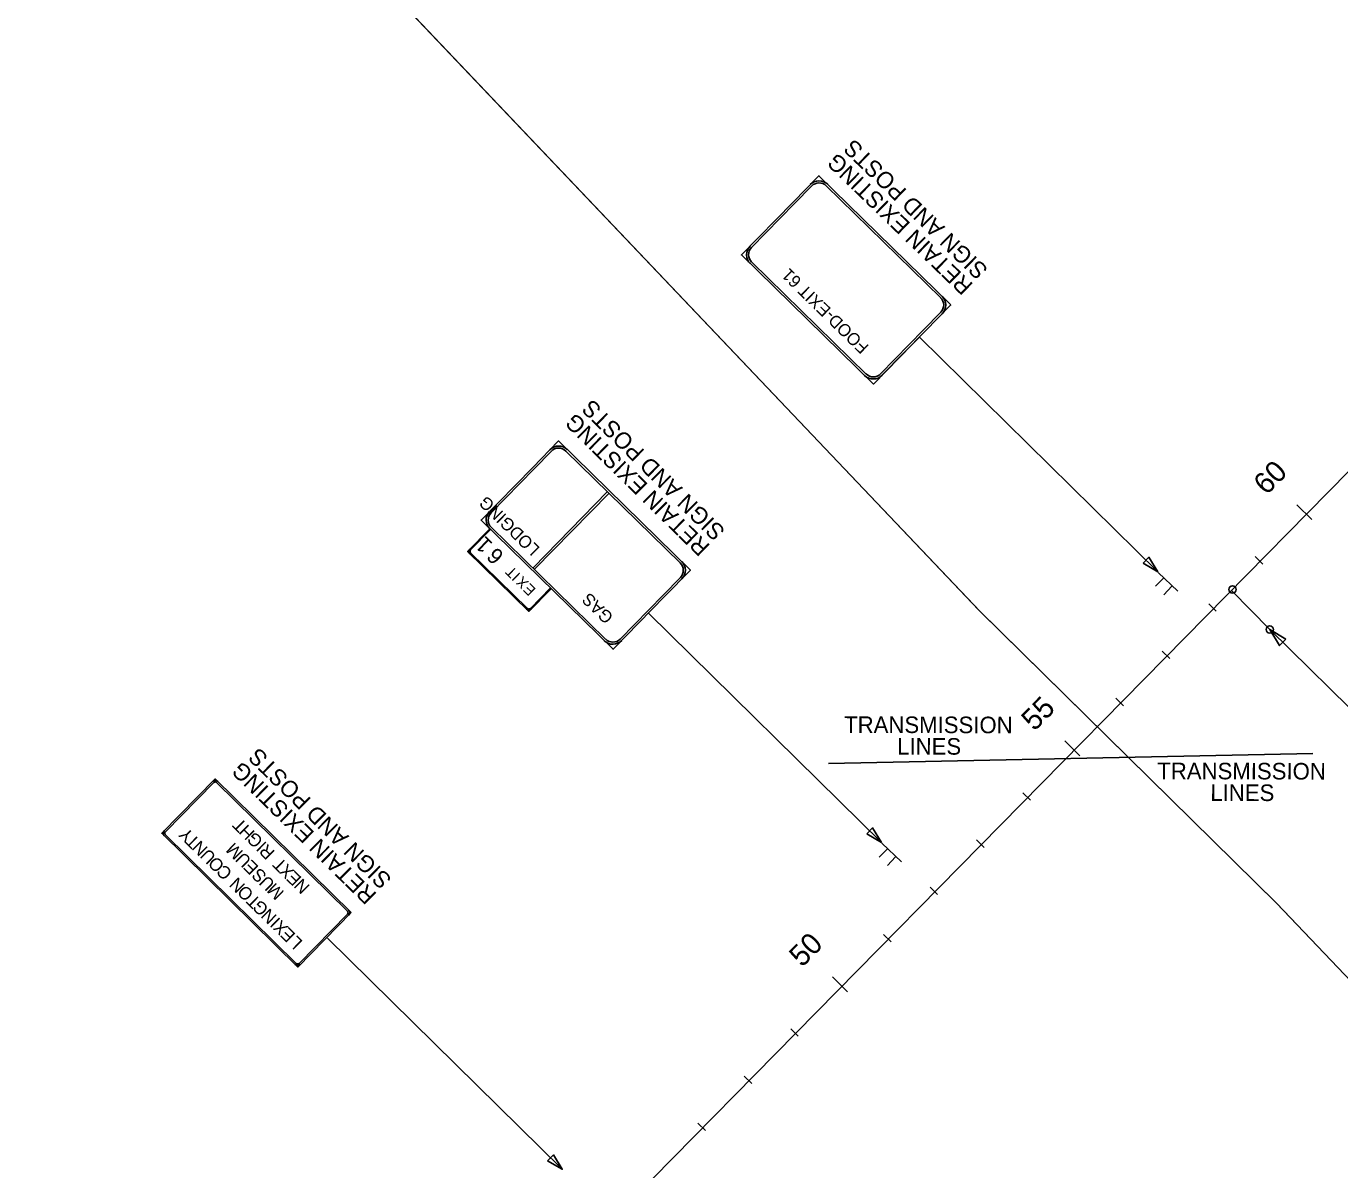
# Model space of a CAD drawing. Extents: x -5665 to 1997148, y 4 to 827579.
# Drawn here: x 1956941 to 1958925, y 794407 to 796134 of the extents above; entities that cross this region are included whole.
import ezdxf

# ---------------------------------------------------------------- set-up
doc = ezdxf.new("R2010")
doc.units = 0
for name, color, linetype in [('RD_HC_CL_Rel', 7, 'Continuous'), ('RD_HC_Data_Tic_Rel', 7, 'Continuous'), ('RD_HC_TX_Rel_Sta50', 7, 'Continuous'), ('RD_PD_Final_TX', 7, 'Continuous'), ('RD_SHT_ShtClip', 7, 'Continuous'), ('RD_SHT_TX', 7, 'Continuous'), ('TR SN EXTRUDED PANEL SIGNS- MOUNTED OVERHEAD', 7, 'Continuous')]:
    doc.layers.add(name, color=color, linetype=linetype)

msp = doc.modelspace()

# ---------------------------------------------------------------- linework, layer by layer
at = {"layer": 'RD_HC_CL_Rel'}
msp.add_line((1957622, 794124.4), (1963740.1, 800343.8), dxfattribs=at)
at = {"layer": 'RD_HC_Data_Tic_Rel'}
for p, q in [((1958882.7, 795388.9), (1958859.9, 795411.3)), ((1958808.3, 795321.8), (1958796.9, 795333)), ((1958738.2, 795250.5), (1958726.8, 795261.7)), ((1958668, 795179.2), (1958656.6, 795190.4)), ((1958597.9, 795107.9), (1958586.5, 795119.1)), ((1958532.1, 795032.4), (1958509.3, 795054.9)), ((1958457.7, 794965.3), (1958446.3, 794976.6)), ((1958387.5, 794894), (1958376.1, 794905.3)), ((1958317.4, 794822.8), (1958306, 794834)), ((1958247.3, 794751.5), (1958235.9, 794762.7)), ((1958181.4, 794676), (1958158.6, 794698.4)), ((1958107, 794608.9), (1958095.6, 794620.1)), ((1958036.9, 794537.6), (1958025.5, 794548.8)), ((1957966.8, 794466.3), (1957955.4, 794477.5))]:
    msp.add_line(p, q, dxfattribs=at)
at = {"layer": 'RD_PD_Final_TX'}
msp.add_lwpolyline([(1958843.4, 795208.6), (1958833.7, 795198.8), (1958818.9, 795223.1)], close=True, dxfattribs=at)
at = {"layer": 'RD_SHT_ShtClip'}
for points in [[(1962404, 800141.4), (1963753.3, 798814), (1964835.2, 797771.3), (1960364.2, 793199.8), (1958829.3, 794809.7), (1958381.6, 795250.1), (1957464.7, 796215.1), (1961650.1, 800469.8)], [(1958379.6, 795252.1), (1958829.6, 794809.5), (1959976.9, 793606), (1955596.7, 789155.3), (1952602.5, 792100.6), (1957064.4, 796636.4)]]:
    msp.add_lwpolyline(points, close=True, dxfattribs=at)
at = {"layer": 'RD_SHT_TX'}
msp.add_line((1958152.5, 795020.6), (1958883.8, 795035.8), dxfattribs=at)
at = {"layer": 'TR SN EXTRUDED PANEL SIGNS- MOUNTED OVERHEAD'}
for p, q in [((1958649.8, 795310.3), (1958289.9, 795664.6)), ((1958646.6, 795288.2), (1958659, 795301.1)), ((1958680, 795280.8), (1958650.5, 795309.3)), ((1958658.8, 795275.5), (1958671.2, 795288.4)), ((1958761.3, 795282), (1958818.9, 795223.1)), ((1958232.4, 794901.5), (1957880.6, 795247.7)), ((1958818.9, 795223.1), (1959187.5, 794860.5)), ((1958229.3, 794879.1), (1958241.6, 794892)), ((1958262.8, 794872.1), (1958232.9, 794900.2)), ((1958241.7, 794866.5), (1958253.9, 794879.5)), ((1957750.5, 794407.9), (1957396, 794756.7))]:
    msp.add_line(p, q, dxfattribs=at)
for points in [[(1958337.4, 795713.2), (1958138.1, 795908.1), (1958099.1, 795868.3)], [(1958127.3, 795892.7), (1958101.3, 795866.1)], [(1958322, 795724), (1958149.2, 795892.9)], [(1958099.1, 795868.3), (1958021.1, 795788.5), (1958220.4, 795593.6), (1958298.4, 795673.3), (1958298.4, 795673.3)], [(1958101.3, 795866.1), (1958036.3, 795799.7)], [(1958036.6, 795777.8), (1958209.3, 795608.8)], [(1958296.2, 795675.5), (1958322.2, 795702.1)], [(1958298.4, 795673.3), (1958337.4, 795713.2), (1958337.4, 795713.2)], [(1958231.2, 795609.1), (1958296.2, 795675.5)], [(1958298.4, 795673.3), (1958233.4, 795606.9)], [(1957944.2, 795312.7), (1957744.9, 795507.7), (1957705.9, 795467.8)], [(1957734.1, 795492.2), (1957708.1, 795465.7)], [(1957928.8, 795323.5), (1957756, 795492.5)], [(1957705.9, 795467.8), (1957627.9, 795388.1), (1957827.3, 795193.1), (1957905.2, 795272.9), (1957905.2, 795272.9)], [(1957708.1, 795465.7), (1957643.1, 795399.2)], [(1957818.7, 795431.2), (1957706.4, 795316.3)], [(1957821.2, 795428.7), (1957708.9, 795313.9)], [(1957641.2, 795375.1), (1957607.7, 795340.8), (1957700.2, 795250.3), (1957733.7, 795284.6), (1957733.7, 795284.6)], [(1957642.4, 795374), (1957612.2, 795343.1)], [(1957643.4, 795377.3), (1957816.1, 795208.4)], [(1957612.2, 795338.6), (1957697.9, 795254.8)], [(1957903, 795275), (1957929, 795301.6)], [(1957905.2, 795272.9), (1957944.2, 795312.7), (1957944.2, 795312.7)], [(1957702.4, 795254.8), (1957732.6, 795285.7)], [(1957838, 795208.6), (1957903, 795275)], [(1957431.8, 794795.5), (1957226.5, 794997.4), (1957145.7, 794915.3), (1957351.1, 794713.3), (1957431.8, 794795.5), (1957431.8, 794795.5), (1957431.8, 794795.5)], [(1957224.5, 794991.9), (1957151.2, 794917.5)], [(1957224.5, 794991.9), (1957224.5, 794991.9), (1957224.5, 794991.9)], [(1957426.3, 794797.5), (1957228.7, 794991.9)], [(1957151.3, 794913.2), (1957348.9, 794718.8)], [(1957151.3, 794913.2), (1957151.3, 794913.2), (1957151.3, 794913.2)], [(1957353.1, 794718.9), (1957426.4, 794793.3)], [(1957426.3, 794797.5), (1957426.3, 794797.5), (1957426.3, 794797.5)], [(1957353.1, 794718.9), (1957353.1, 794718.9), (1957353.1, 794718.9)]]:
    msp.add_lwpolyline(points, dxfattribs=at)
for points in [[(1958627.8, 795323.3), (1958636.4, 795332.2), (1958649.8, 795310.3)], [(1958210.4, 794914.4), (1958219.1, 794923.3), (1958232.4, 794901.5)], [(1957728.4, 794420.9), (1957737.1, 794429.7), (1957750.5, 794407.9)]]:
    msp.add_lwpolyline(points, close=True, dxfattribs=at)
for centre in [(1958762.6, 795283.5), (1958818.9, 795223.1)]:
    msp.add_circle(centre, 5.54, dxfattribs=at)
for centre, radius, start, end in [((1958138.4, 795881.9), 18.6, 45.6377, 135.6379), ((1958138.4, 795881.9), 15.5, 45.6377, 135.6379), ((1958047.4, 795788.8), 18.6, 135.6376, 225.6379), ((1958047.4, 795788.8), 15.5, 135.6376, 225.6379), ((1958311.1, 795712.9), 15.5, 315.6375, 45.6377), ((1958311.1, 795712.9), 18.6, 315.6375, 45.6377), ((1958220.2, 795619.9), 18.6, 225.6379, 315.6375), ((1958220.2, 795619.9), 15.5, 225.6379, 315.6375), ((1957745.2, 795481.4), 18.6, 45.6377, 135.6379), ((1957745.2, 795481.4), 15.5, 45.6377, 135.6379), ((1957654.2, 795388.4), 18.6, 135.6376, 225.6379), ((1957654.2, 795388.4), 15.5, 135.6376, 225.6379), ((1957614.5, 795340.9), 4.8, 135.6376, 225.6379), ((1957614.5, 795340.9), 3.2, 135.6376, 225.6379), ((1957917.9, 795312.5), 15.5, 315.6375, 45.6377), ((1957917.9, 795312.5), 18.6, 315.6375, 45.6377), ((1957700.1, 795257.1), 4.8, 225.6379, 315.6375), ((1957700.1, 795257.1), 3.2, 225.6379, 315.6375), ((1957827, 795219.4), 18.6, 225.6379, 315.6375), ((1957827, 795219.4), 15.5, 225.6379, 315.6375), ((1957226.6, 794989.8), 5.4, 45.4705, 135.4707), ((1957226.6, 794989.8), 3, 45.4705, 135.4707), ((1957153.4, 794915.4), 5.4, 135.4705, 225.4707), ((1957153.4, 794915.4), 3, 135.4705, 225.4707), ((1957424.2, 794795.4), 3, 315.4703, 45.4705), ((1957424.2, 794795.4), 5.4, 315.4703, 45.4705), ((1957351, 794721), 5.4, 225.4707, 315.4703), ((1957351, 794721), 3, 225.4707, 315.4703)]:
    msp.add_arc(centre, radius, start, end, dxfattribs=at)

# ---------------------------------------------------------------- texts
at = {"layer": 'RD_HC_TX_Rel_Sta50'}
for s, p in [('60', (1958814.1, 795424.8)), ('55', (1958463.5, 795068.4)), ('50', (1958112.8, 794711.9))]:
    msp.add_text(s, height=32, rotation=45.4705, dxfattribs=at).set_placement(p)
at = {"layer": 'RD_SHT_TX'}
for s, p in [('TRANSMISSION', (1958176.2, 795066.9)), ('LINES', (1958256.3, 795034.2)), ('TRANSMISSION', (1958649.1, 794997)), ('LINES', (1958729.2, 794964.2))]:
    msp.add_text(s, height=25, rotation=359.866, dxfattribs=at).set_placement(p)
at = {"layer": 'TR SN EXTRUDED PANEL SIGNS- MOUNTED OVERHEAD'}
for s, height, rotation, p in [('SIGN AND POSTS', 25, 135.9277, (1958394.9, 795767.3)), ('RETAIN EXISTING', 25, 135.9277, (1958372.3, 795744)), ('FOOD-EXIT 61', 18.587, 135.6376, (1958214.8, 795650.9)), ('SIGN AND POSTS', 25, 135.4569, (1957998.1, 795372.7)), ('RETAIN EXISTING', 25, 135.4569, (1957975.2, 795349.5)), ('LODGING', 18.59, 135.6376, (1957717.9, 795345.9)), ('1', 24, 135.6376, (1957646.8, 795352.8)), ('6', 24, 135.6376, (1957664, 795336)), ('T', 16, 135.6376, (1957684, 795310.9)), ('I', 16, 135.6376, (1957688.6, 795306.4)), ('X', 16, 135.6376, (1957700.9, 795294.4)), ('E', 16, 135.6376, (1957711.7, 795283.8)), ('GAS', 18.59, 135.6376, (1957829.1, 795243.1)), ('SIGN AND POSTS', 25, 135.4569, (1957494.5, 794846.7)), ('RETAIN EXISTING', 25, 135.4569, (1957471.7, 794823.5)), ('T', 19.2, 135.4705, (1957275.9, 794928.7)), ('H', 19.2, 135.4705, (1957287.7, 794917.1)), ('Y', 19.2, 135.4705, (1957195.6, 794913.4)), ('T', 19.2, 135.4705, (1957204.8, 794904.3)), ('N', 19.2, 135.4705, (1957216.6, 794892.8)), ('G', 19.2, 135.4705, (1957300.1, 794904.9)), ('U', 19.2, 135.4705, (1957229, 794880.6)), ('M', 19.2, 135.4705, (1957269.9, 794887.5)), ('U', 19.2, 135.4705, (1957282.3, 794875.3)), ('I', 19.2, 135.4705, (1957305.4, 794899.6)), ('R', 19.2, 135.4705, (1957317.8, 794887.4)), ('O', 19.2, 135.4705, (1957241.8, 794867.9)), ('C', 19.2, 135.4705, (1957253.6, 794856.4)), ('E', 19.2, 135.4705, (1957293.2, 794864.5)), ('T', 19.2, 135.4705, (1957336.4, 794869.1)), ('X', 19.2, 135.4705, (1957347.3, 794858.4)), ('N', 19.2, 135.4705, (1957273, 794837.2)), ('S', 19.2, 135.4705, (1957305.6, 794852.3)), ('U', 19.2, 135.4705, (1957318, 794840.1)), ('E', 19.2, 135.4705, (1957358.2, 794847.7)), ('N', 19.2, 135.4705, (1957370.6, 794835.5)), ('O', 19.2, 135.4705, (1957285.9, 794824.6)), ('M', 19.2, 135.4705, (1957331.8, 794826.6)), ('T', 19.2, 135.4705, (1957296.8, 794813.9)), ('G', 19.2, 135.4705, (1957308.5, 794802.3)), ('N', 19.2, 135.4705, (1957320.9, 794790.1)), ('I', 19.2, 135.4705, (1957326.3, 794784.8)), ('X', 19.2, 135.4705, (1957338.1, 794773.3)), ('E', 19.2, 135.4705, (1957349, 794762.5)), ('L', 19.2, 135.4705, (1957359.9, 794751.8))]:
    msp.add_text(s, height=height, rotation=rotation, dxfattribs=at).set_placement(p)

doc.saveas('drawing.dxf')
